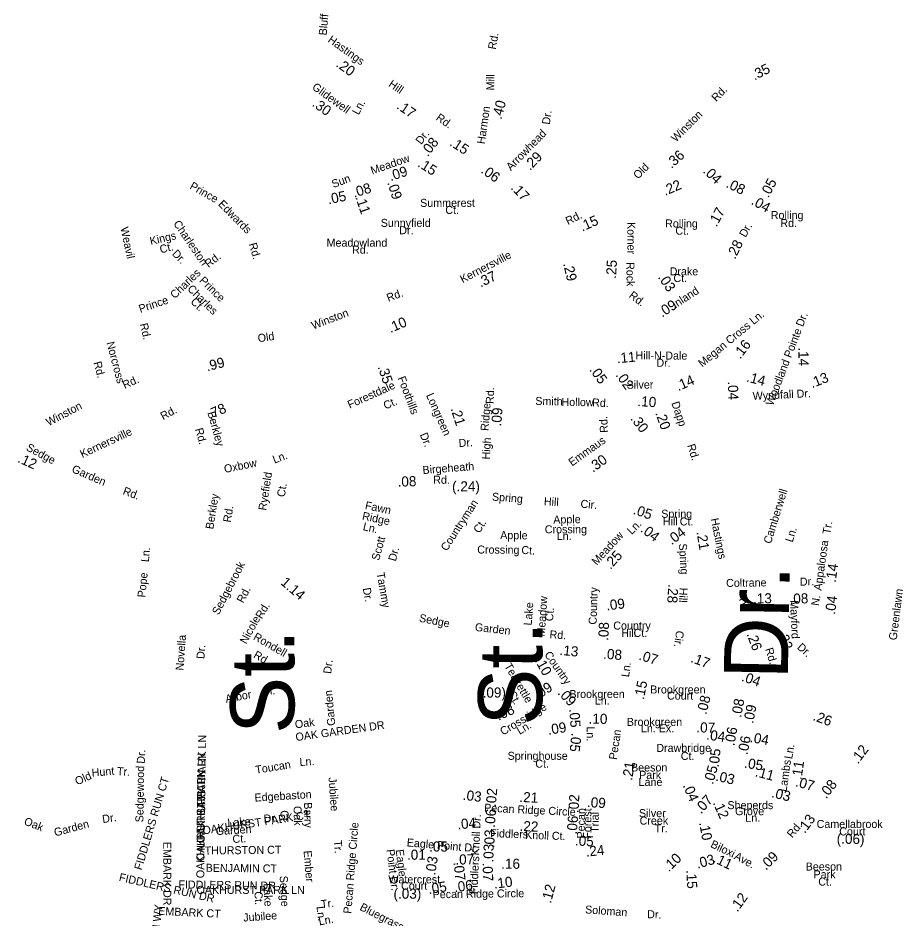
# Model space of a CAD drawing. Extents: x 1553981 to 1780076, y 812965 to 996873.
# Drawn here: x 1637536 to 1638839, y 847356 to 848692 of the extents above; entities that cross this region are included whole.
import ezdxf

# ---------------------------------------------------------------- set-up
doc = ezdxf.new("R2010")
doc.units = 0
for name, color, linetype in [('Exist Road Non-System Type 51 Label', 7, 'Continuous'), ('Exist Road Secondary Mileage Hundredths English Label', 7, 'Continuous'), ('Map Preparation Border Antique Large Shape', 7, 'Continuous')]:
    doc.layers.add(name, color=color, linetype=linetype)

msp = doc.modelspace()

# ---------------------------------------------------------------- texts
at = {"layer": 'Exist Road Non-System Type 51 Label'}
for s, height, rotation, p in [('Prince', 11.88, 330.4251, (1637789.9, 848439.7)), ('Edwards', 11.88, 314.6813, (1637832.3, 848415.3)), ('Weavil', 11.88, 282.0599, (1637688, 848381)), ('Charleston', 11.88, 304.3316, (1637766.1, 848387.3)), ('Kings', 11.87, 13.0662, (1637733.2, 848355.5)), ('Ct.', 11.87, 13.0662, (1637747.9, 848343.2)), ('Rd.', 11.88, 286.2462, (1637878.6, 848357.1)), ('Dr.', 11.88, 313.7607, (1637763.9, 848341.8)), ('Rd.', 11.87, 37.3743, (1637818.8, 848321.4)), ('Charles', 11.88, 43.7512, (1637768.8, 848275.1)), ('Prince', 11.88, 315.3446, (1637804.4, 848301.9)), ('Charles', 11.88, 315.3446, (1637786.6, 848289.5)), ('Prince', 11.88, 18.68, (1637717.7, 848254.8)), ('Ct.', 11.88, 315.3446, (1637791.3, 848270.5)), ('Rd.', 11.88, 282.6821, (1637717, 848238.3)), ('Norcross', 11.88, 284.9018, (1637667.3, 848210.6)), ('Rd.', 11.88, 284.9018, (1637648, 848181.2)), ('Forestdale', 11.88, 24.1918, (1638028.4, 848112.6)), ('Ct.', 11.88, 24.1918, (1638081.6, 848111.3)), ('Smith', 11.87, 358.8423, (1638303.7, 848118.4)), ('Hollow', 11.88, 359.5348, (1638342.6, 848116.8)), ('Rd.', 11.88, 357.2916, (1638387.9, 848116.2)), ('Berkley', 11.88, 285.5149, (1637817.1, 848106.9)), ('Rd.', 11.88, 285.5149, (1637798.8, 848082.4)), ('Oxbow', 11.87, 11.6351, (1637843.2, 848017.3)), ('Ln.', 11.87, 20.3601, (1637916.6, 848031.2)), ('Ryefield', 11.88, 81.1469, (1637904.4, 847961.1)), ('Ct.', 11.88, 81.1469, (1637932, 847981.1)), ('Camberwell', 11.88, 72.7978, (1638653.4, 847911.4)), ('Berkley', 11.88, 81.0543, (1637825.9, 847933.2)), ('Spring', 11.88, 355.5185, (1638239.1, 847976.5)), ('Hill', 11.88, 356.1729, (1638316.2, 847969.6)), ('Rd.', 11.88, 81.0543, (1637852, 847943.4)), ('Fawn', 11.88, 348.0816, (1638050.4, 847964)), ('Countryman', 11.88, 57.0386, (1638172.5, 847900.5)), ('Cir.', 11.88, 355.3091, (1638370.5, 847966)), ('Ridge', 11.88, 348.0816, (1638046.1, 847948.3)), ('Apple', 11.87, 1.0802, (1638330.6, 847942.2)), ('Ln.', 11.88, 346.9831, (1638047.2, 847932.7)), ('Ct.', 11.88, 57.0386, (1638220.8, 847926.9)), ('Crossing', 11.87, 0.2635, (1638317.9, 847927.8)), ('Apple', 11.87, 359.4514, (1638251.7, 847919.3)), ('Ln.', 11.88, 359.5035, (1638335.6, 847918.1)), ('Ln.', 11.88, 72.7978, (1638685.6, 847913.7)), ('Scott', 11.87, 74.8247, (1638071.9, 847886.6)), ('Ln.', 11.88, 84.3353, (1637730.2, 847884.7)), ('Dr.', 11.87, 74.8247, (1638096.7, 847885.6)), ('Crossing', 11.87, 359.4514, (1638217.6, 847897.9)), ('Ct.', 11.88, 356.4011, (1638282.8, 847897.4)), ('Sedgebrook', 11.87, 62.4877, (1637833.9, 847805.9)), ('Pope', 11.88, 84.5295, (1637725.1, 847832.2)), ('Tammy', 11.88, 279.9243, (1638068.2, 847868.8)), ('Dr.', 95, 88.9162, (1638678.4, 847710.6)), ('Rd.', 11.87, 62.4877, (1637870.5, 847823.4)), ('Dr.', 11.88, 279.9243, (1638047.7, 847846.2)), ('Meadow', 11.88, 85.9931, (1638317.7, 847774.4)), ('Greenlawn', 11.87, 82.7376, (1638839.9, 847768.7)), ('Rd.', 11.88, 58.8852, (1637897.8, 847799.9)), ('Lake', 11.88, 85.9931, (1638298.4, 847790.8)), ('Ct.', 11.88, 85.9931, (1638330.1, 847797.1)), ('Nicole', 11.88, 61.1997, (1637874.9, 847762.6)), ('Rondell', 11.87, 329.9629, (1637884.2, 847771)), ('St.', 95, 89.7213, (1638313.8, 847642.1)), ('Novella', 11.88, 85.8962, (1637781.7, 847724)), ('St.', 95, 89.934, (1637946.2, 847630.1)), ('Dr.', 11.87, 85.92, (1637812.7, 847741.1)), ('Rd.', 11.87, 329.9629, (1637884.5, 847744.1)), ('Dr.', 11.88, 83.3362, (1638000.8, 847718.9)), ('Pl.', 11.87, 6.8695, (1637899.9, 847686.9)), ('Arbor', 11.88, 10.6913, (1637845, 847676.3)), ('Garden', 11.88, 95.574, (1638007.2, 847642.8)), ('Oak', 11.87, 7.7647, (1637947.9, 847638.3)), ('OAK GARDEN DR', 11.875, 7.952, (1637948.8, 847619.5)), ('OAKHURST PARK LN', 11.875, 89.1348, (1637813.1, 847468.2)), ('Dr.', 11.88, 87.3718, (1637724.2, 847585.8)), ('OAKHURST PARK LN', 11.875, 89.5054, (1637812.8, 847441.3)), ('Ln.', 11.87, 4.0308, (1637954.3, 847582.5)), ('Hunt', 11.88, 5.1188, (1637646, 847566.7)), ('Tr.', 11.88, 355.995, (1637682.7, 847569.3)), ('Sedgewood', 11.88, 89.1518, (1637722.2, 847498.9)), ('Toucan', 11.88, 9.355, (1637889.3, 847570.9)), ('Old', 11.88, 24.024, (1637623.9, 847553.8)), ('FIDDLERS RUN CT', 11.875, 73.3457, (1637719.6, 847427.3)), ('OAKHURST PARK LN', 11.875, 89.5054, (1637812.6, 847416.1)), ('Jubilee', 11.88, 274.0681, (1637996.9, 847565.4)), ('Edgebaston', 11.88, 3.5727, (1637887.5, 847529.7)), ('Barry', 11.88, 271.5366, (1637960.5, 847528.6)), ('OAKHURST PARK CT', 11.875, 8.4006, (1637810.8, 847481)), ('Ct.', 11.88, 271.5366, (1637925.6, 847516.8)), ('Oak', 11.88, 271.5366, (1637945, 847523.1)), ('Oak', 11.88, 338.5668, (1637544, 847496.1)), ('Garden', 11.88, 15.0874, (1637591.4, 847478)), ('Dr.', 11.87, 7.9285, (1637662, 847497.9)), ('Lake', 11.88, 3.5727, (1637847.3, 847492.6)), ('Dr.', 11.88, 3.5727, (1637901, 847498.5)), ('Pecan Ridge Circle', 11.875, 85.3627, (1638030.7, 847363.1)), ('Garden', 11.88, 3.5727, (1637830, 847480)), ('Ct.', 11.88, 3.5727, (1637854.8, 847468.3)), ('Tr.', 11.88, 274.779, (1638004.7, 847472)), ('EMBARK DR', 11.88, 270.0698, (1637751.7, 847470.1)), ('THURSTON CT', 11.875, 0.698, (1637813.3, 847451.2)), ('Point Dr.', 11.88, 276.9606, (1638082.9, 847458.4)), ('Eagle ', 11.88, 276.9606, (1638096.6, 847458.2)), ('Ember', 11.88, 274.7847, (1637959.9, 847456.7)), ('BENJAMIN CT', 11.875, 359.3621, (1637814.6, 847425.7)), ('FIDDLERS RUN DR', 11.875, 346.9654, (1637685.2, 847412.4)), ('Sedge', 11.88, 272.8192, (1637924.5, 847419.5)), ('FIDDLERS RUN DR', 11.875, 359.2339, (1637774.1, 847401)), ('Lake', 11.88, 272.8192, (1637900.4, 847408.3)), ('Ct.', 11.88, 272.8192, (1637887, 847396.4)), ('Tr.', 11.88, 6.6867, (1637986.4, 847371.6)), ('Bluegrass', 11.88, 333.0342, (1638042.3, 847369.5)), ('MEREDITH WY', 11.875, 84.1352, (1637739.1, 847264.2)), ('EMBARK CT', 11.87, 357.2332, (1637744.1, 847361.8)), ('Jubilee', 11.88, 4.0681, (1637870.8, 847351.7)), ('Ln.', 11.88, 276.0995, (1637979.1, 847374)), ('Ln.', 11.88, 10.7927, (1637983.4, 847346))]:
    msp.add_text(s, height=height, rotation=rotation, dxfattribs=at).set_placement(p)
msp.add_text('OAKHURST PARK LN', height=11.875, dxfattribs=at).set_placement((1637801.1, 847392.8))
at = {"layer": 'Exist Road Secondary Mileage Hundredths English Label'}
for s, rotation, p in [('.20', 324.5498, (1638006.8, 848621.3)), ('.35', 27.5301, (1638629.2, 848599.5)), ('.30', 324.0716, (1637971.5, 848562.7)), ('.40', 75.3676, (1638253.5, 848541)), ('.17', 325.4177, (1638096.9, 848558.9)), ('.08', 51.9662, (1638144.2, 848485.9)), ('.15', 327.0998, (1638175.6, 848504.1)), ('.29', 45.6922, (1638296, 848465.3)), ('.36', 41.5852, (1638505.8, 848468.3)), ('.15', 327.8897, (1638128.1, 848472.8)), ('.09', 17.7725, (1638089.1, 848450.4)), ('.06', 324.6838, (1638221.9, 848463.7)), ('.04', 316.6258, (1638551.6, 848464)), ('.08', 17.2739, (1638035.1, 848425.7)), ('.09', 287.8066, (1638083.9, 848448.2)), ('.22', 23.3674, (1638496.5, 848428.4)), ('.08', 334.0618, (1638585.6, 848441.9)), ('.05', 62.2888, (1638649.7, 848424.6)), ('.05', 11.5193, (1637997, 848416)), ('.17', 313.3966, (1638266.5, 848439.7)), ('.11', 288.8469, (1638036.6, 848426.3)), ('.04', 330.4008, (1638623, 848416.8)), ('.17', 61.4337, (1638572.6, 848381.5)), ('.15', 24.0866, (1638373.5, 848375.3)), ('.28', 63.9186, (1638600.3, 848333.5)), ('.25', 86.7503, (1638423.5, 848305.3)), ('.37', 25.7947, (1638222.6, 848292.3)), ('.29', 283.363, (1638345, 848327.8)), ('.03', 303.6145, (1638485.2, 848307.8)), ('.09', 32.5172, (1638491.9, 848247.8)), ('.10', 23.1737, (1638089, 848224.9)), ('.16', 52.3743, (1638607.8, 848185.6)), ('.11', 5.188, (1638425.3, 848180.1)), ('.14', 270.8598, (1638694.1, 848203.7)), ('.99', 14.2471, (1637817, 848168.1)), ('.35', 288.7709, (1638069.7, 848174.8)), ('.05', 305.9668, (1638383.3, 848170.4)), ('.02', 304.5517, (1638422.4, 848162.6)), ('.14', 23.0925, (1638515.9, 848138.7)), ('.14', 345.2467, (1638616.1, 848153.3)), ('.13', 21.9763, (1638714.6, 848143)), ('.04', 272.2009, (1638589.4, 848153.2)), ('.10', 356.1398, (1638455, 848116.7)), ('.78', 24.3747, (1637821.4, 848096.5)), ('.09', 85.4303, (1638253.1, 848086)), ('.21', 287.6282, (1638178, 848112.7)), ('.30', 307.4765, (1638444.1, 848097.7)), ('.20', 289.7708, (1638481.6, 848106.3)), ('.12', 335.6274, (1637534.5, 848033.9)), ('.30', 35.4231, (1638389.3, 848017.6)), ('.08', 1.9791, (1638099.7, 847996.9)), ('(.24)', 359.7585, (1638180.3, 847990.1)), ('.05', 341.236, (1638447.9, 847956.9)), ('.04', 322.8143, (1638458.7, 847931.2)), ('.04', 37.1085, (1638506.2, 847909.8)), ('.21', 279.679, (1638542.9, 847929.7)), ('.25', 47.4954, (1638415.3, 847873.4)), ('.14', 81.9704, (1638749.4, 847854.1)), ('1.14', 319.1021, (1637924.8, 847853.2)), ('.28', 266.1181, (1638501.3, 847852.5)), ('.13', 0.8245, (1638627, 847823.6)), ('.08', 1.9324, (1638681.3, 847823.1)), ('.04', 82.4013, (1638748.4, 847806.6)), ('.09', 6.9051, (1638409.8, 847813.3)), ('.08', 87.612, (1638412.1, 847768)), ('.26', 290.611, (1638617.1, 847778.3)), ('.22', 291.0044, (1638662.7, 847779.5)), ('.13', 353.9806, (1638339.2, 847747.6)), ('.08', 355.7392, (1638404.1, 847741.9)), ('.07', 343.0062, (1638456.4, 847740.6)), ('.10', 299.2962, (1638302.5, 847739.3)), ('.17', 339.2268, (1638533.3, 847737.2)), ('.04', 340.6218, (1638608.7, 847709.2)), ('(.09)', 0.294, (1638219, 847684)), ('.09', 33.5617, (1638307.6, 847680.4)), ('.15', 78.6996, (1638464.8, 847680.3)), ('.09', 312.9332, (1638336.1, 847690.3)), ('.08', 76.3105, (1638557.5, 847658.3)), ('.08', 24.7944, (1638249.3, 847649.6)), ('.08', 79.4955, (1638609.1, 847653.7)), ('.09', 79.3042, (1638627.1, 847644.8)), ('.05', 273.9807, (1638354.2, 847667.1)), ('.10', 358.841, (1638382.8, 847645.5)), ('.26', 339.8524, (1638714.6, 847650.9)), ('.09', 9.0032, (1638323.3, 847628.8)), ('.07', 357.8773, (1638542.6, 847632.7)), ('.04', 352.6885, (1638557, 847621.9)), ('.06', 80.1933, (1638599.1, 847611.7)), ('.05', 263.6537, (1638357.7, 847632.1)), ('.06', 79.3042, (1638618.6, 847598.4)), ('.04', 349.9066, (1638621.6, 847618.2)), ('.05', 83.5353, (1638575.9, 847580)), ('.12', 53.499, (1638782.7, 847584.6)), ('.05', 350.5962, (1638613.1, 847580.3)), ('.21', 80.9084, (1638447.4, 847560.4)), ('.05', 74.3592, (1638567.4, 847554.3)), ('.11', 345.5026, (1638629.1, 847567.5)), ('.11', 81.793, (1638698.8, 847561.6)), ('.03', 347.357, (1638570.5, 847561)), ('.07', 344.6705, (1638688.8, 847552.8)), ('.04', 293.4334, (1638522.3, 847553.7)), ('.08', 51.8469, (1638735.4, 847533.2)), ('.03', 353.6542, (1638195.6, 847532.4)), ('.02', 85.2406, (1638245.1, 847521.3)), ('.21', 356.867, (1638279.9, 847529.4)), ('.02', 87.5127, (1638368, 847512.4)), ('.07', 47.7303, (1638549.7, 847510.7)), ('.03', 346.5747, (1638653.5, 847536.3)), ('.09', 356.2326, (1638380.1, 847521.8)), ('.12', 294.0248, (1638566.9, 847528)), ('.06', 85.7674, (1638243.7, 847490.7)), ('.04', 5.3518, (1638188.7, 847488.5)), ('.22', 357.255, (1638280.2, 847486.3)), ('.06', 86.0583, (1638365.4, 847480.7)), ('.13', 53.4467, (1638703.7, 847481.6)), ('.03', 89.046, (1638243.1, 847460.5)), ('.10', 280.9793, (1638546.7, 847498.5)), ('.05', 356.4205, (1638362.3, 847464.9)), ('(.06)', 358.6641, (1638750.9, 847467.5)), ('.05', 359.7744, (1638146.2, 847455.7)), ('.03', 89.1636, (1638241.7, 847439.2)), ('.24', 5.9575, (1638379.3, 847448)), ('.03', 81.5185, (1638155.2, 847419.9)), ('.07', 0.9288, (1638185.3, 847436.3)), ('.10', 43.8037, (1638501.9, 847424.7)), ('.03', 15.9107, (1638544.6, 847430.1)), ('.11', 334.1573, (1638566.6, 847440.6)), ('.09', 44.6362, (1638646, 847427.1)), ('.07', 276.3925, (1638182.4, 847439.6)), ('.07', 272.3223, (1638225.4, 847439.1)), ('.10', 6.999, (1638243, 847400.5)), ('.15', 273.1773, (1638527.8, 847428)), ('.05', 9.2178, (1638145.8, 847392.5)), ('.06', 7.4113, (1638184.2, 847395.3)), ('.12', 75.081, (1638326.9, 847377.9)), ('.12', 54.2163, (1638603.7, 847365))]:
    msp.add_text(s, height=15, rotation=rotation, dxfattribs=at).set_placement(p)
for s, p in [('.01', (1638113.4, 847443.5)), ('.16', (1638253.2, 847430.1)), ('(.03)', (1638093.4, 847385.7))]:
    msp.add_text(s, height=15, dxfattribs=at).set_placement(p)
at = {"layer": 'Map Preparation Border Antique Large Shape'}
for s, height, rotation, p in [('Bluff', 11.88, 85.4002, (1637994.2, 848666.3)), ('Hastings', 11.88, 324.2242, (1637994.9, 848657.8)), ('Rd.', 11.88, 79.765, (1638245, 848645.1)), ('Mill', 11.87, 88.841, (1638242.8, 848584.9)), ('Glidewell', 11.88, 324.0718, (1637971.5, 848587.7)), ('Hill', 11.88, 325.4177, (1638084.9, 848591.8)), ('Rd.', 11.88, 45.2388, (1638572.3, 848567.5)), ('Ln.', 11.88, 61.7399, (1638041.6, 848547.7)), ('Harmon', 11.87, 81.8405, (1638228.7, 848504.8)), ('Rd.', 11.88, 325.2986, (1638155.3, 848542)), ('Dr.', 11.88, 81.9377, (1638325.2, 848533.7)), ('Winston', 11.88, 44.9718, (1638512.3, 848507.6)), ('Arrowhead', 11.88, 45.6922, (1638267.6, 848465.1)), ('Dr.', 11.88, 52.8965, (1638134.5, 848503.8)), ('Meadow', 11.88, 19.3254, (1638061.8, 848460)), ('Old', 11.88, 45.3864, (1638456.3, 848452.6)), ('Sun', 11.87, 20.6513, (1638004.3, 848440)), ('Rd.', 11.88, 26.4844, (1638352.3, 848385.1)), ('Korner', 11.87, 270.3871, (1638440.3, 848389.7)), ('Dr.', 11.88, 60.8723, (1638615.9, 848366)), ('Kernersville', 11.875, 27.6312, (1638196, 848298.7)), ('Rock', 11.88, 270.1332, (1638439.1, 848330.3)), ('Rd.', 11.88, 20.3782, (1638085.7, 848271.2)), ('Rd.', 11.88, 322.6395, (1638441.7, 848278.8)), ('Inland', 11.88, 33.1875, (1638511.6, 848261.1)), ('Winston', 11.88, 20.9347, (1637974.3, 848230)), ('Megan Cross Ln.', 11.875, 39.5819, (1638551.5, 848173.7)), ('Woodland Pointe Dr.', 11.875, 69.0593, (1638656.2, 848116.3)), ('Old', 11.88, 8.3897, (1637892.8, 848211.2)), ('Hill-N-Dale', 11.875, 359.741, (1638452.6, 848185.9)), ('Dr.', 11.88, 359.7118, (1638483.5, 848175)), ('Rd.', 11.88, 24.3263, (1637694.5, 848141.8)), ('Foothills', 11.88, 290.7552, (1638099.4, 848158.3)), ('Silver', 11.88, 0.4968, (1638439.3, 848142.3)), ('Rd.', 11.88, 88.3501, (1638242.1, 848119.6)), ('Wyndfall Dr.', 11.875, 2.7697, (1638626.6, 848125.7)), ('Longreen', 11.88, 293.9382, (1638141.4, 848132.7)), ('Winston', 11.88, 27.6806, (1637581.6, 848086.6)), ('Rd.', 11.88, 28.232, (1637751.5, 848095.5)), ('Ridge', 11.88, 85.4303, (1638234.2, 848079.4)), ('Dapp', 11.87, 288.7902, (1638505.6, 848121.2)), ('Rd.', 11.88, 92.4122, (1638411.6, 848077.2)), ('Kernersville', 11.875, 25.1635, (1637631.6, 848039.4)), ('Dr.', 11.88, 292.8357, (1638132.1, 848074.2)), ('Sedge', 11.88, 331.7168, (1637547.3, 848051.6)), ('Dr.', 11.88, 3.4968, (1638190.4, 848055.8)), ('High', 11.88, 86.7922, (1638236.3, 848037.1)), ('Emmaus', 11.88, 35.4233, (1638358.3, 848026.8)), ('Rd.', 11.88, 288.0679, (1638529, 848058.3)), ('Birgeheath', 11.88, 4.4447, (1638136.9, 848015.7)), ('Garden', 11.88, 336.5561, (1637614.9, 848019)), ('Rd.', 11.88, 339.7574, (1637690.8, 847986.1)), ('Ln.', 11.88, 44.9981, (1638446.8, 847925.2)), ('Hastings', 11.87, 281.4767, (1638564, 847949.2)), ('Tr.', 11.88, 80.6965, (1638741.5, 847925.7)), ('Meadow', 11.88, 47.4954, (1638394.9, 847879.6)), ('Appaloosa', 11.88, 81.9704, (1638728.4, 847842.4)), ('Spring', 11.87, 273.5673, (1638516.8, 847912.4)), ('Coltrane', 11.87, 0.8245, (1638587, 847848.2)), ('Dr.', 11.88, 1.9324, (1638696.5, 847850)), ('Country', 11.87, 88.1484, (1638394.7, 847792.2)), ('Hill', 11.88, 266.8628, (1638518.1, 847847.4)), ('Hill', 11.88, 300.6261, (1638605.5, 847830)), ('N.', 11.87, 81.4916, (1638724.6, 847819.7)), ('Mayford', 11.88, 272.2705, (1638681.9, 847828.4)), ('Sedge', 11.88, 348.8317, (1638130.6, 847796.9)), ('Garden', 11.88, 353.6709, (1638213.7, 847783.1)), ('Rd.', 11.87, 356.8723, (1638324.7, 847772)), ('Cir.', 11.87, 261.8602, (1638512.9, 847784)), ('Dr.', 11.88, 318.0637, (1638691.4, 847757.5)), ('Country', 11.88, 304.8266, (1638316.6, 847747.8)), ('Rd.', 11.88, 286.8403, (1638644.7, 847756.1)), ('Teakettle', 11.88, 300.6738, (1638257.3, 847731)), ('Ln.', 11.88, 82.1527, (1638442.8, 847713.9)), ('Ct.', 11.88, 300.6738, (1638262.8, 847689.8)), ('Crossridge', 11.88, 30.7761, (1638255.9, 847627.6)), ('Ln.', 11.88, 30.1738, (1638280.4, 847628.7)), ('Ln.', 11.88, 270.1677, (1638380, 847641.4)), ('Pecan', 11.88, 81.5085, (1638424.6, 847591.3)), ('Ln.', 11.88, 80.6963, (1638684.9, 847592.3)), ('Lambs', 11.88, 81.793, (1638676.6, 847543.9)), ('Pecan Ridge Circle', 11.875, 357.2425, (1638227.7, 847514.9)), ('Pecan', 11.88, 89.3146, (1638377.3, 847475)), ('Forest', 11.88, 89.3146, (1638386.6, 847474.7)), ('Trial', 11.88, 89.3146, (1638397.7, 847483.4)), ('Knoll Dr.', 11.88, 87.2761, (1638220.2, 847449.8)), ('Fiddlers', 11.88, 357.977, (1638236.5, 847477.1)), ('Knoll Ct.', 11.88, 358.1057, (1638288.5, 847474.6)), ('Rd.', 11.88, 50.2025, (1638685.1, 847475.1)), ('Eagle Point Dr.', 11.875, 355.2321, (1638112.7, 847463.4)), ('Biloxi', 11.87, 334.1573, (1638562.7, 847462.7)), ('Fiddlers', 11.87, 86.9549, (1638217.7, 847392.2)), ('Ave.', 11.88, 331.3703, (1638597.8, 847445.4)), ('Pecan Ridge Circle', 11.875, 0.7138, (1638151.5, 847386.3)), ('Soloman', 11.87, 355.8228, (1638377.4, 847364)), ('Dr.', 11.88, 358.0644, (1638469.6, 847356.9))]:
    msp.add_text(s, height=height, rotation=rotation, dxfattribs=at).set_placement(p)
for s, height, p in [('Summerest', 11.88, (1638132.9, 848412.2)), ('Ct.', 11.88, (1638170.3, 848401.7)), ('Sunnyfield', 11.88, (1638074.4, 848382.5)), ('Rolling', 11.88, (1638496.4, 848381.6)), ('Rolling', 11.88, (1638653.2, 848394.1)), ('Rd.', 11.88, (1638667.4, 848382.3)), ('Dr.', 11.88, (1638101.9, 848371.6)), ('Ct.', 11.88, (1638511.6, 848370.9)), ('Meadowland', 11.88, (1637994.1, 848353.1)), ('Rd.', 11.88, (1638031.8, 848342.7)), ('Drake', 11.88, (1638503.2, 848310.6)), ('Ct.', 11.88, (1638508.8, 848300.6)), ('Rd.', 11.88, (1638152.3, 848001.3)), ('Spring', 11.88, (1638490.7, 847950.9)), ('Hill', 11.88, (1638493.2, 847939.8)), ('Ct.', 11.88, (1638518.1, 847939.5)), ('Country', 11.88, (1638419.5, 847785)), ('Hill', 11.88, (1638431.4, 847774)), ('Ct.', 11.88, (1638449.6, 847774.2)), ('Brookgreen', 11.88, (1638474.3, 847690.2)), ('Brookgreen', 11.88, (1638354.4, 847683.5)), ('Ln.', 11.88, (1638392.1, 847673.8)), ('Court', 11.88, (1638499.2, 847681.1)), ('Brookgreen', 11.88, (1638439.6, 847642.1)), ('Ln. Ex.', 11.88, (1638460.5, 847632.7)), ('Drawbridge', 11.88, (1638483.4, 847603.5)), ('Springhouse', 11.875, (1638262.7, 847591.8)), ('Ct.', 11.88, (1638303.8, 847580.1)), ('Ct.', 11.88, (1638519.7, 847591.6)), ('Beeson', 11.88, (1638445.9, 847574.5)), ('Park', 11.88, (1638457.9, 847563.4)), ('Lane', 11.88, (1638457.1, 847552.9)), ('Sheperds', 11.88, (1638588.9, 847518.6)), ('Silver', 11.88, (1638457.6, 847506.7)), ('Grove', 11.88, (1638600.2, 847509.6)), ('Ln.', 11.88, (1638615.4, 847499.9)), ('Creek', 11.88, (1638458.6, 847495.6)), ('Camellabrook', 11.875, (1638721.3, 847490.6)), ('Tr.', 11.88, (1638481, 847484.2)), ('Court', 11.88, (1638754.8, 847479.6)), ('Beeson', 11.88, (1638705, 847427.5)), ('Watercrest', 11.88, (1638085.7, 847408.5)), ('Park', 11.88, (1638716.7, 847415.9)), ('Court', 11.88, (1638104.6, 847399.1)), ('Ct.', 11.88, (1638723.7, 847405.1))]:
    msp.add_text(s, height=height, dxfattribs=at).set_placement(p)

doc.saveas('drawing.dxf')
